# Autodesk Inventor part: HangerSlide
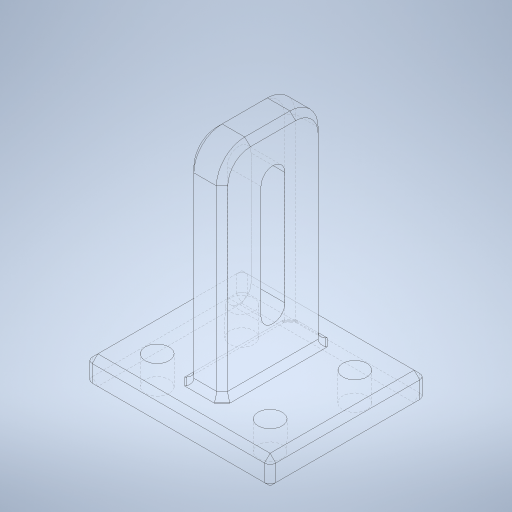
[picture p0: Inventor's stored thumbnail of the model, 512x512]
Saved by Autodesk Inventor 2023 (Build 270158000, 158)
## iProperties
Created: 2023-11
Part Number: HangerSlide
Material: Generic
Document SubType Name: Modeling
Designer: tornqvih
Density: 1 g/cm^3
Appearance: Default
Mass: 59.4859 g
Surface Area: 168.489 cm^2
Volume: 59.4859 cm^3
Author: tornqvih
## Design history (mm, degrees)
sketch "Sketch1"
  geometry: L1 (-32.5, 27.5)-(32.5, 27.5); L2 (32.5, 27.5)-(32.5, -27.5); L3 (32.5, -27.5)-(-32.5, -27.5); L4 (-32.5, -27.5)-(-32.5, 27.5); L5 (-32.5, 27.5)-(32.5, -27.5); L6 (32.5, 27.5)-(-32.5, -27.5); 1 further point
  constraints: 12 end point, 2 midpoint, 2 parallel, 1 horizontal, 1 perpendicular
  dimensions: "d4" = 65 distance of L1.start L1.end; "d5" = 55 distance of L3.end L1.start
extrude "Extrusion2" new body sketch "Sketch1" distance "d6" = 10; taper "d7" = 0 deg
sketch "Sketch2"
  geometry: L1 (10, 27.5)-(10, -27.5) reference; L2 (10, -18)-(85, -18); L3 (85, -18)-(85, 18); L4 (85, 18)-(10, 18); L5 (0, -27.5)-(10, -27.5) reference; L6 (-16.6, 0)-(99.6, 0) reference; 2 further points
  constraints: 6 end point, 3 perpendicular, 1 point on line, 1 symmetric about line
  dimensions: "d93" = 75 distance between parallel lines of L1 L3; "d96" = 36 distance between parallel lines of L2 L4
extrude "Extrusion3" join sketch "Sketch2" stored distance "d13" = 12; taper "d14" = 0 deg
sketch "Sketch3"
  geometry: L1 (-4.25, 69)-(-4.25, 29); L2 (4.25, 29)-(4.25, 69); L3 (18, 85)-(-18, 85) reference; L4 (-27.5, 10)-(27.5, 10) reference; L5 (0, -17)-(0, 102) reference; A1 r 4.25 centre (0, 69) between (4.25, 69) and (-4.25, 69); A2 r 4.25 centre (0, 29) between (-4.25, 29) and (4.25, 29); 2 further points; 1 other entity
  constraints: 4 end point, 4 point on circle, 4 tangent, 2 centre point, 2 point on line, 1 parallel, 1 other
  dimensions: "d15" = 8.5 distance between parallel lines of L2 L1; "d16" = 40 distance of A1.centre A2.centre; "d75" = 16 distance from line of L3 A1.centre
extrude "Extrusion4" cut sketch "Sketch3" distance "d20" = 12; taper "d21" = 0 deg
fillet "Fillet1" dims "d22" = 10
fillet "Fillet3" dims "d74" = 2
sketch "Sketch9"
  geometry: L1 (-45.5, 0)-(45.5, 0) reference; L2 (-30.5, 27.5)-(30.5, 27.5) reference; L3 (-32.5, -25.5)-(-32.5, 25.5) reference; L4 (0, -38.5)-(0, 38.5) reference; 5 further points
  constraints: 3 symmetric about line
  dimensions: "d92" = 40 distance of point (20, -15) point (-20, -15); "d94" = 30 distance of point (-20, -15) point (-20, 15)
hole "Hole3" sketch "Sketch9" at (-20, 15), (20, 15), (-20, -15), (20, -15) diameter "d85" = 8.5; stored, may be unused: countersink angle "d89" = 90 deg, drill point angle "d91" = 118 deg; dims "d86" = 6, "d87" = 4, "d88" = 2, "d90" = 8
fillet "Fillet4" dims "d95" = 2
chamfer "Chamfer1" distance "d97" = 2; stored, may be unused: second distance "d98" = 2, angle "d99" = 45 deg
body "Solid2"
